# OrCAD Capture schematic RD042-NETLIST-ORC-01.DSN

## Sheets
1 3: size A3
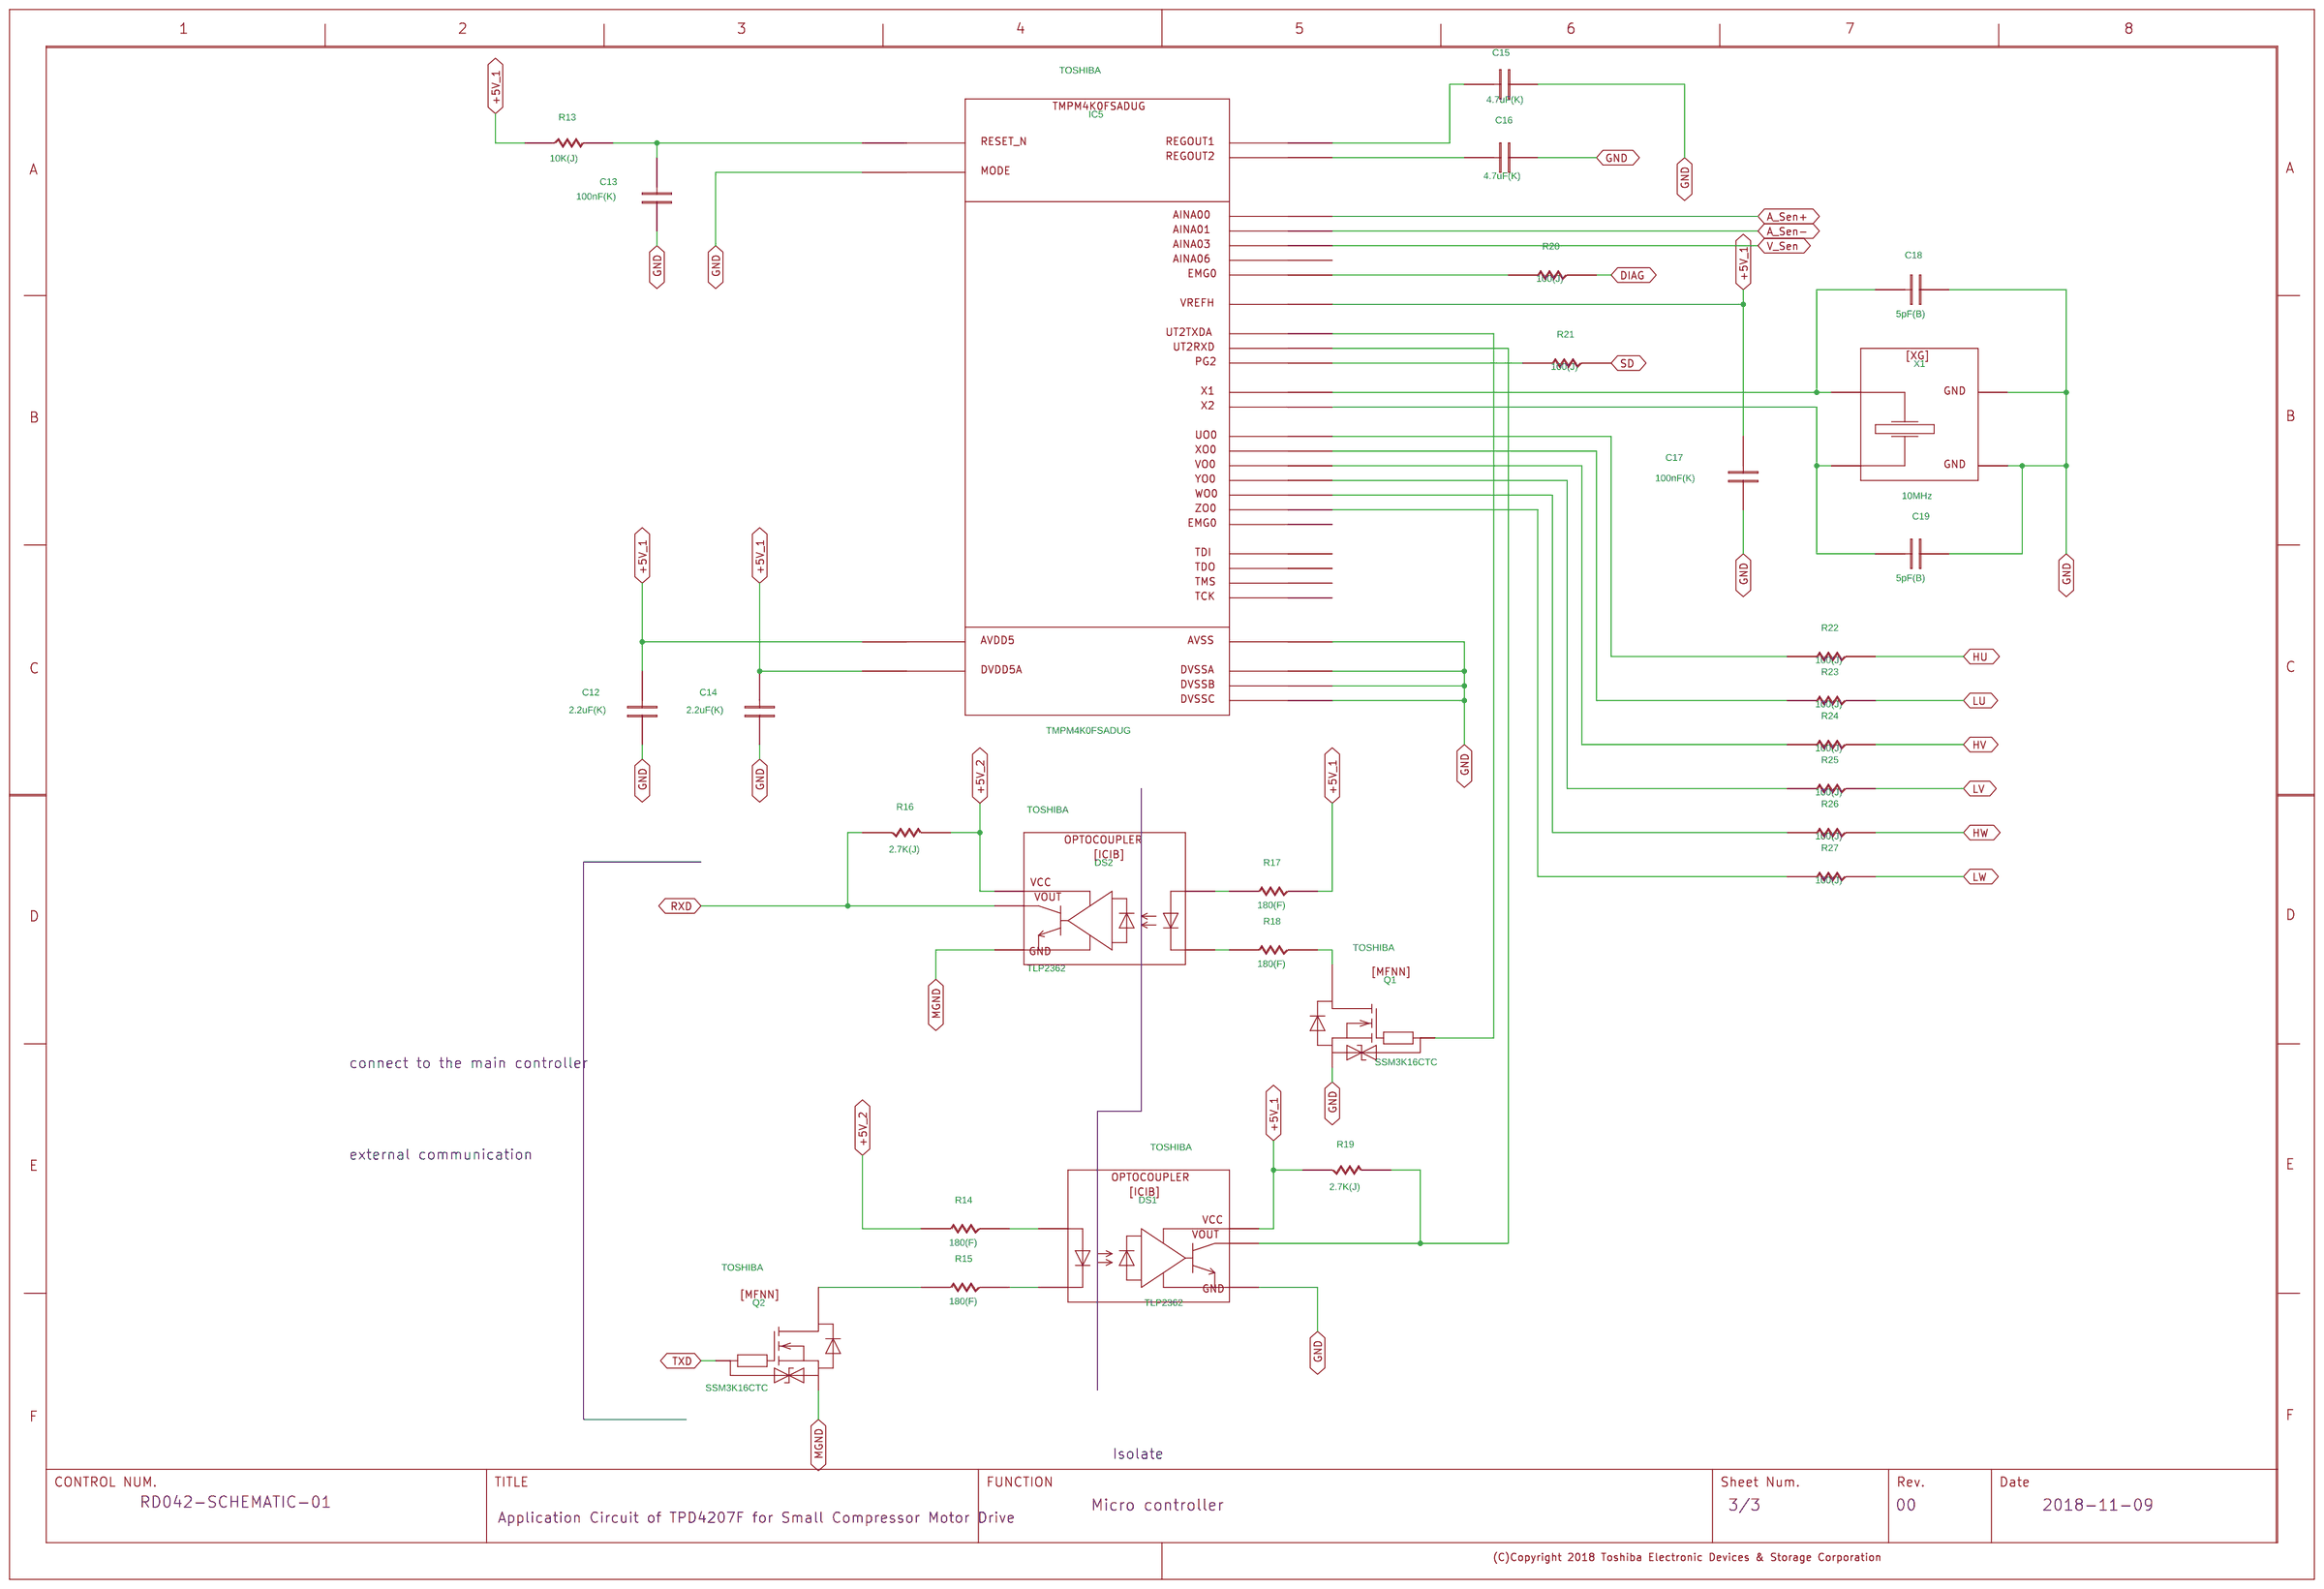
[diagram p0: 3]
2 2: size A3
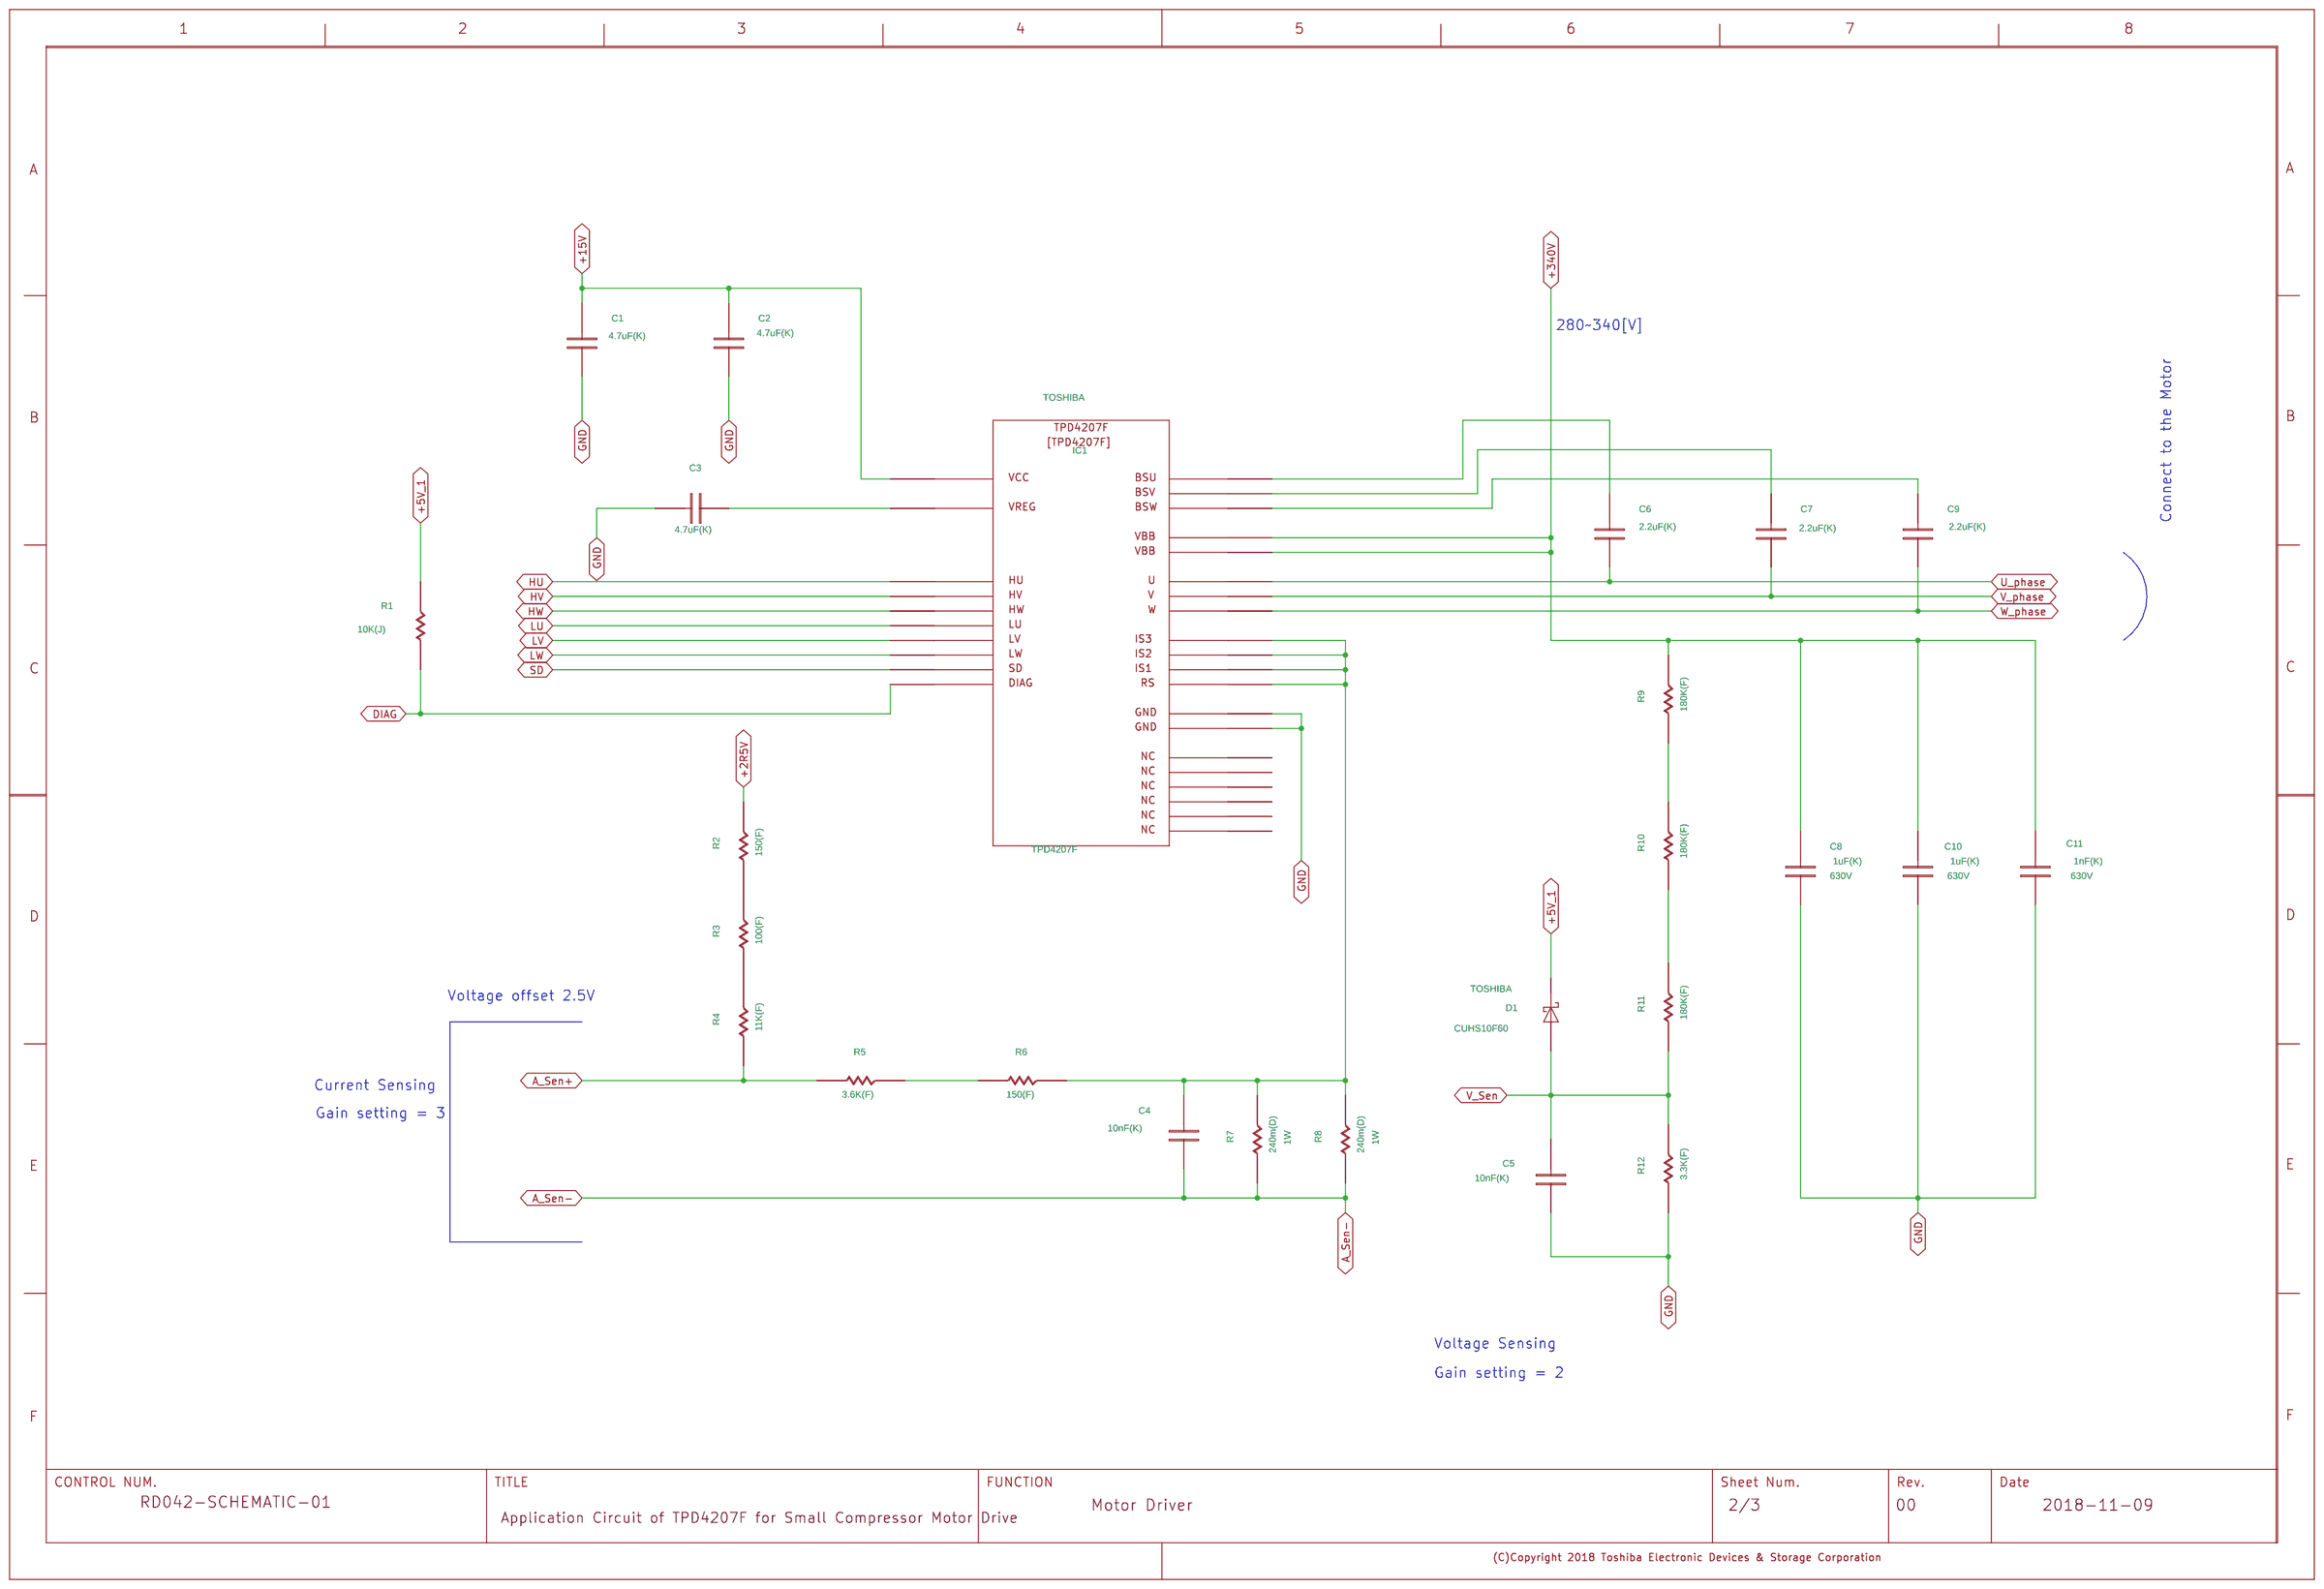
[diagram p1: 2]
3 1
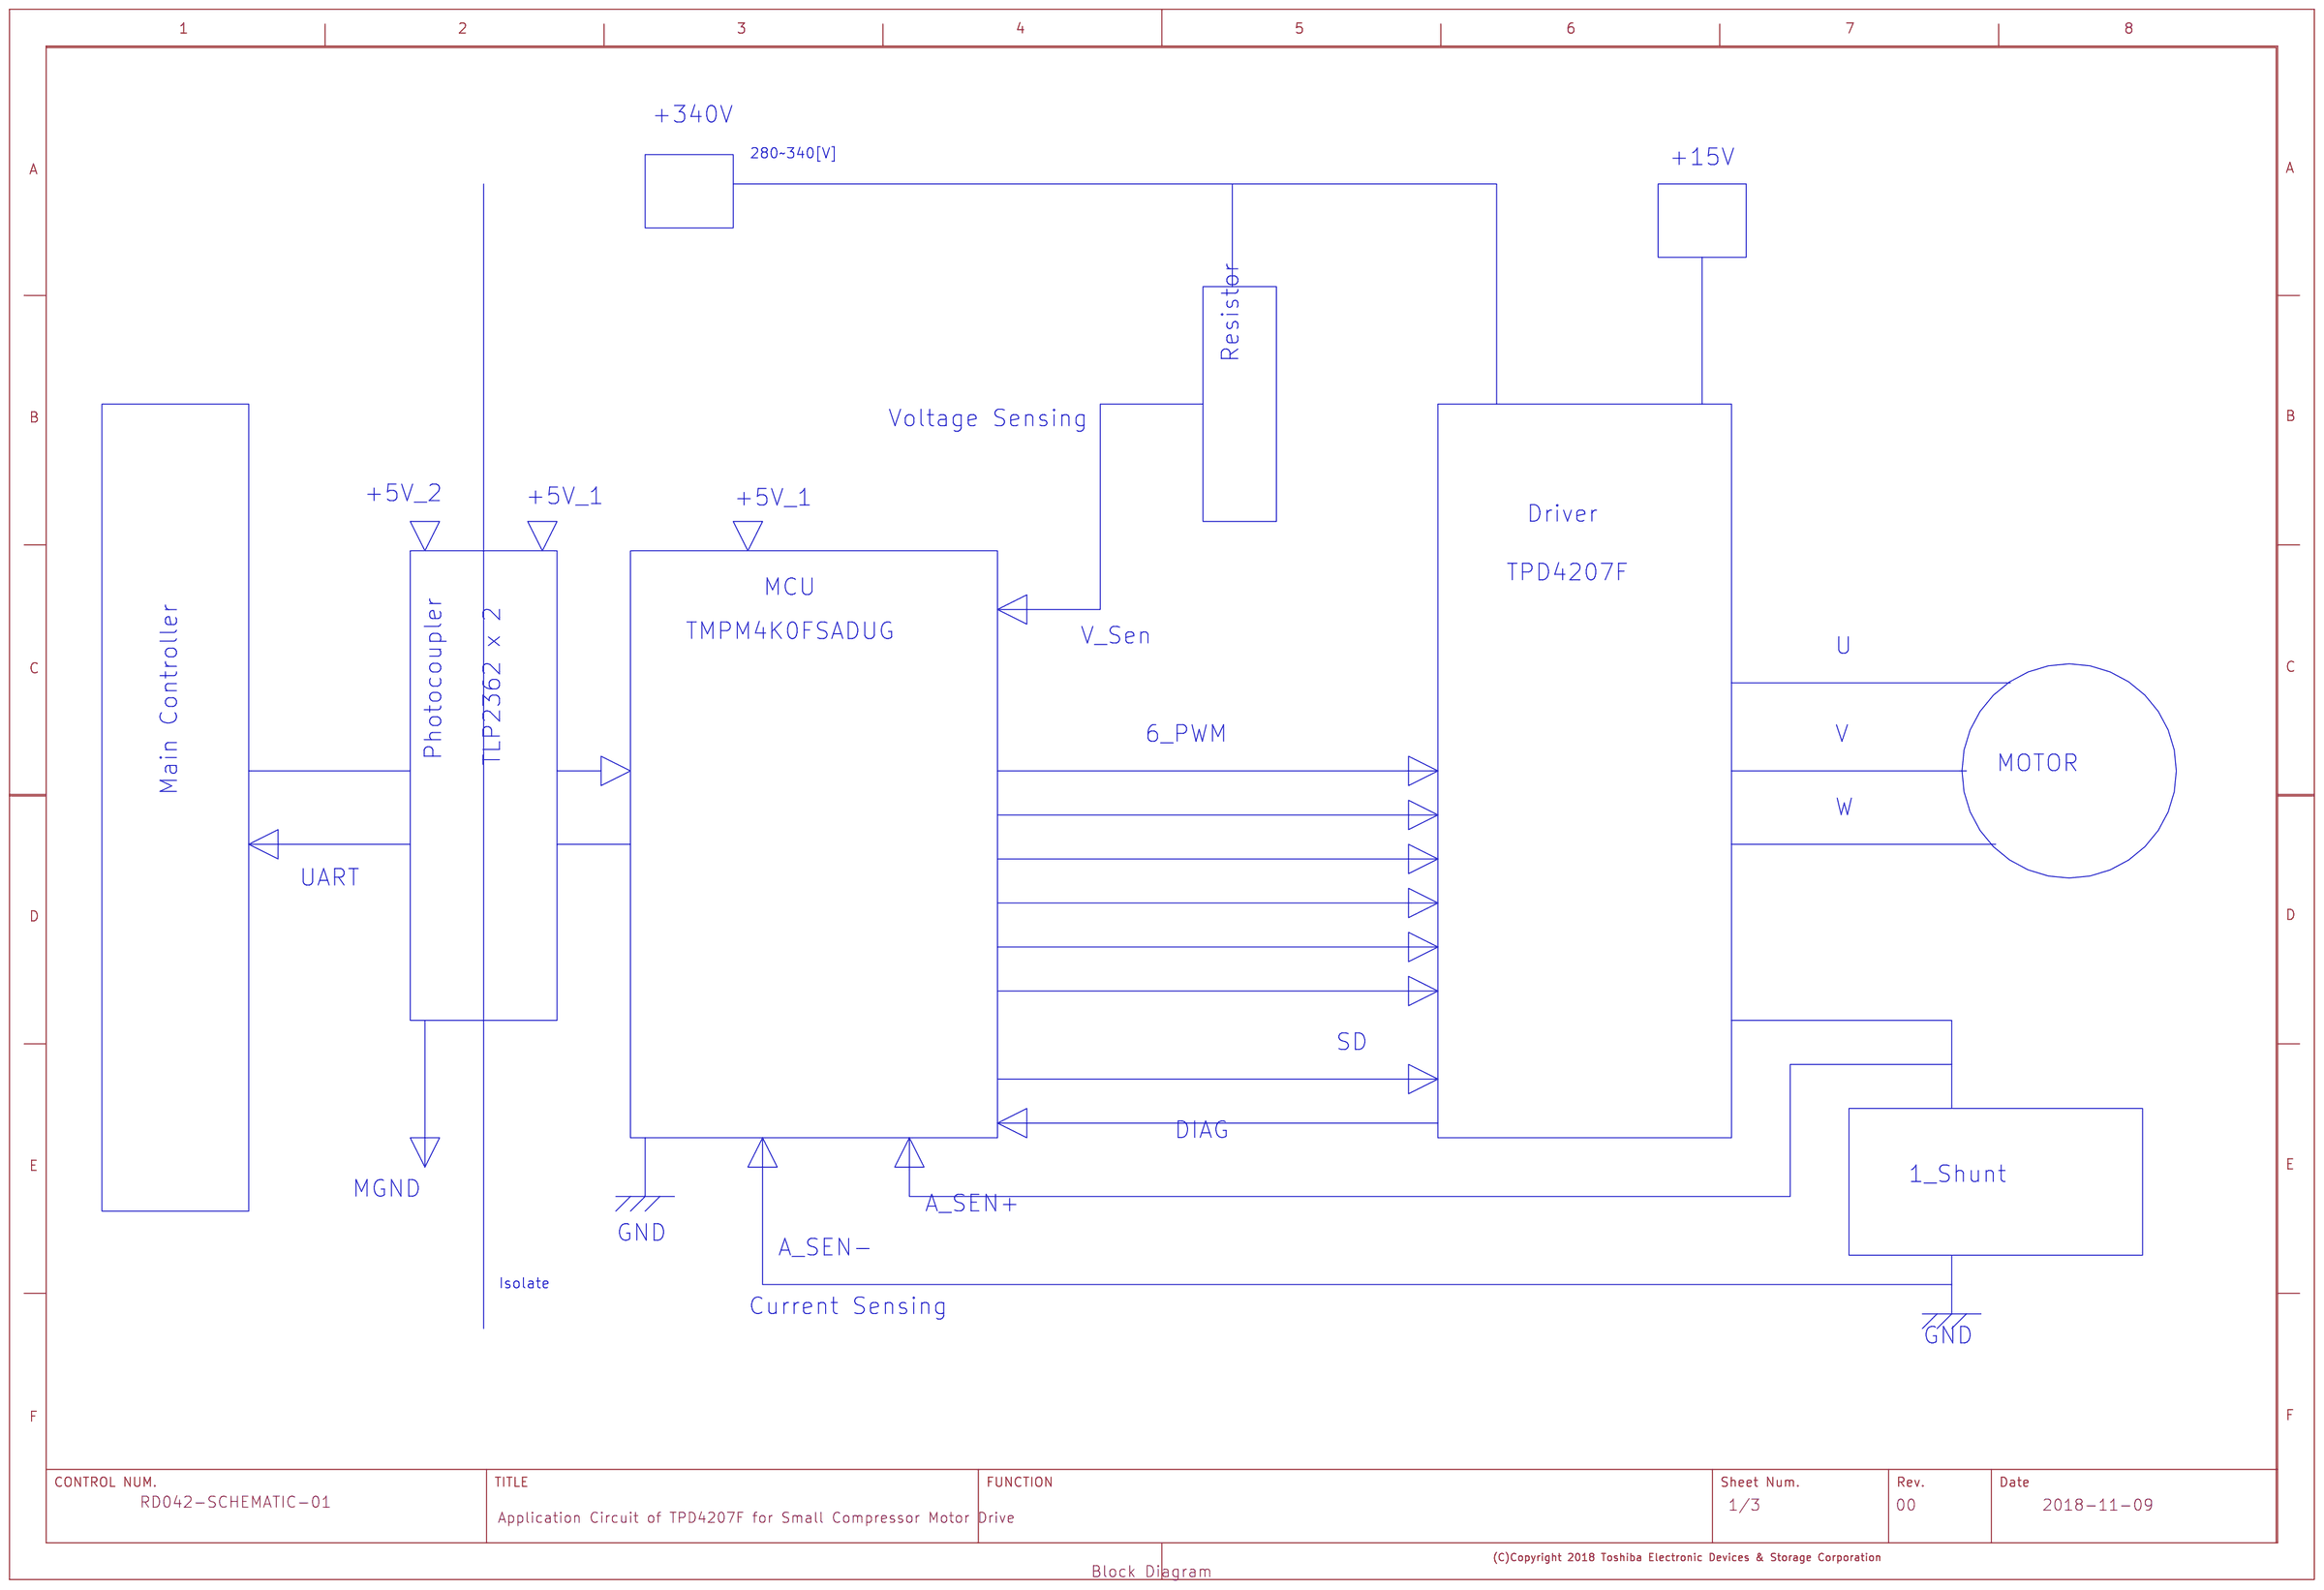
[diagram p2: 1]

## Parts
sheet 1
U?#2  WAKU_DEF100_2018
sheet 2
C1  C
C2  C
C3  C
C4  C
C5  C
C6  C
C7  C
C8  C
C9  C
C10  C
C11  C
D1  SBD
IC1  S-TPD4207F
R1  R
R2  R
R3  R
R4  R
R5  R
R6  R
R7  R
R8  R
R9  R
R10  R
R11  R
R12  R
U?#1  WAKU_DEF100_2018
sheet 3
C12  C
C13  C
C14  C
C15  C
C16  C
C17  C
C18  C
C19  C
DS1  ICIB
DS2  ICIB
IC5  TMPM4K0FSADUG-3
Q1  MFNN
Q2  MFNN
R13  R
R14  R
R15  R
R16  R
R17  R
R18  R
R19  R
R20  R
R21  R
R22  R
R23  R
R24  R
R25  R
R26  R
R27  R
U?#3  WAKU_DEF100_2018
X1  XG

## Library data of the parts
U?#2 = WAKU_DEF100_2018: AUTHOR: g4302510; COMPONENTTYPE: 2; DATE: 2018-11-09; DESIGNED: RD042-SCHEMATIC-01; DRAWINGNUMBER: RD042-SCHEMATIC-01; FUNCTION: Block Diagram; REVISION: 00; SAVEAREA0: -45080,-4508,463680,304612; SHEETNUMBER: 1/3; TIME: 10:32:20; TITLE: Application Circuit of TPD4207F for Small Compressor Motor Drive; UPDATEDATE: 2018/12/03; UPDATETIME: 17:07:27; UPDATEUSER: g4302510
C1-C3 = C: ADSCNVFLAG: ON; ADSCOMPONENTNAME: C_2012; ADSMODELNAME: s_GRM21BB31E475KA75L; ALLGREEN: 0:O[; CAPACITANCETOLE: K; CDBNAME: GDM030002448; CDMASTERCADCELG: KC0006; COMP: GDM030002448; COMPONENTNAME: GDM030002448_package; COMPONENTTYPE: 4; FNAPPROVALRESUG: B:i(GREEN); FNCANCELLATIONG: 0:Žg—p‰Â; FNENVIRONMANTRG: N:¢²¸; FNLEADFREETHET1GT2GMCTH1: 2_0_N; FUNCN: GDM030002448; GCOUNT: 1; ICX_PART_MODEL: CON_4.7U; MAXGCOUNT: 1; NOMINALCAPACITA: 4.7u; OUMECLASSIFICATION: ƒZƒ‰ƒ~ƒbƒNƒRƒ“ƒfƒ“ƒT; OUMEMAKER: MRT ºc»ì; OUMEMAKERKATAMEI: GRM21BB31E475KA75L; PMPRODUCTSTYPEG: HD1; QUADMODEL: CON_4.7U; RATEDVOLTAGE: 25; SIZECODESMD: 2012; SQ_PART_MODEL: CON_4.7U; TEMPCHARACTERI2: B; VAL1: 4.7uF(K); VAL2: 25V; VAL3: GRM21BB31E475KA75L
C4 C5 = C: ADSCNVFLAG: ON; ADSCOMPONENTNAME: C_3216; ADSMODELNAME: s_ECJ3FB2J103K; ALLGREEN: N:¢²¸; CAPACITANCETOLE: K; CDBNAME: K0301630; CDMASTERCADCELG: KC0014; COMP: K0301630; COMPONENTNAME: K0301630_package; COMPONENTTYPE: 4; FNAPPROVALRESUG: 5:bè(KR[h); FNCANCELLATIONG: 0:Žg—p‰Â; FNENVIRONMANTRG: N:¢²¸; FNLEADFREETHET1GT2GMCTH1: N_N_N; FUNCN: K0301630; GCOUNT: 1; ICX_PART_MODEL: CON_10N; MAXGCOUNT: 1; NOMINALCAPACITA: 10n; OUMECLASSIFICATION: ƒZƒ‰ƒ~ƒbƒNƒRƒ“ƒfƒ“ƒT; OUMEMAKER: NAE pi\jbNGNgjbNfoCX; OUMEMAKERKATAMEI: ECJ3FB2J103K; QUADMODEL: CON_10N; RATEDVOLTAGE: 630; SIZECODESMD: 3216; SQ_PART_MODEL: CON_10N; TEMPCHARACTERI2: B; VAL1: 10nF(K); VAL2: 630V; VAL3: ECJ3FB2J103K
C6 C7 C9 = C: ADSCNVFLAG: ON; ADSCOMPONENTNAME: C_2012; ADSMODELNAME: s_GRM219B31E225KA75D; ALLGREEN: 0:O[; CAPACITANCETOLE: K; CDBNAME: GDM030002425; CDMASTERCADCELG: KC0006; COMP: GDM030002425; COMPONENTNAME: GDM030002425_package; COMPONENTTYPE: 4; FNAPPROVALRESUG: B:i(GREEN); FNCANCELLATIONG: 0:Žg—p‰Â; FNENVIRONMANTRG: N:¢²¸; FNLEADFREETHET1GT2GMCTH1: 2_0_N; FUNCN: GDM030002425; GCOUNT: 1; ICX_PART_MODEL: CON_2.2U; MAXGCOUNT: 1; NOMINALCAPACITA: 2.2u; OUMECLASSIFICATION: ƒZƒ‰ƒ~ƒbƒNƒRƒ“ƒfƒ“ƒT; OUMEMAKER: MRT ºc»ì; OUMEMAKERKATAMEI: GRM219B31E225KA75D; PMPRODUCTSTYPEG: HD1; QUADMODEL: CON_2.2U; RATEDVOLTAGE: 25; SIZECODESMD: 2012; SQ_PART_MODEL: CON_2.2U; TEMPCHARACTERI2: B; VAL1: 2.2uF(K); VAL2: 25V; VAL3: GRM219B31E225KA75D
C8 C10 = C: ADSCNVFLAG: ON; ALLGREEN: 1:ñO[; CAPACITANCETOLE: K; CDBNAME: GDM030000013; CDMASTERCADCELG: RD0001; COMP: GDM030000013; COMPONENTNAME: GDM030000013_package; COMPONENTTYPE: 4; FNAPPROVALRESUG: 4:i; FNCANCELLATIONG: 0:Žg—p‰Â; FNENVIRONMANTRG: N:¢²¸; FNLEADFREETHET1GT2GMCTH1: 9_N_N; FUNCN: GDM030000013; GCOUNT: 1; ICX_PART_MODEL: CON_1U; MAXGCOUNT: 1; NOMINALCAPACITA: 1u; OUMECLASSIFICATION: ƒtƒBƒ‹ƒƒRƒ“ƒfƒ“ƒT; OUMEMAKER: NAE pi\jbNGNgjbNfoCX; OUMEMAKERKATAMEI: ECQE6105KF; QUADMODEL: CON_1U; RATEDVOLTAGE: 630; SIZECODESMD: DIP; SQ_PART_MODEL: CON_1U; VAL1: 1uF(K); VAL2: 630V; VAL3: ECQE6105KF
C11 = C: ADSCNVFLAG: ON; ALLGREEN: 1:ñO[; CAPACITANCETOLE: K; CDBNAME: GDM030000013; CDMASTERCADCELG: RD0001; COMP: GDM030000013; COMPONENTNAME: GDM030000013_package; COMPONENTTYPE: 4; FNAPPROVALRESUG: 4:i; FNCANCELLATIONG: 0:Žg—p‰Â; FNENVIRONMANTRG: N:¢²¸; FNLEADFREETHET1GT2GMCTH1: 9_N_N; FUNCN: GDM030000013; GCOUNT: 1; ICX_PART_MODEL: CON_1U; MAXGCOUNT: 1; NOMINALCAPACITA: 1u; OUMECLASSIFICATION: ƒtƒBƒ‹ƒƒRƒ“ƒfƒ“ƒT; OUMEMAKER: NAE pi\jbNGNgjbNfoCX; OUMEMAKERKATAMEI: ECQE6105KF; QUADMODEL: CON_1U; RATEDVOLTAGE: 630; SIZECODESMD: DIP; SQ_PART_MODEL: CON_1U; VAL1: 1nF(K); VAL2: 630V; VAL3: ECQE6105KF
D1 = SBD: ADSCNVFLAG: ON; ADSCOMPONENTNAME: D_SBD; ADSMODELNAME: s_CUS551V30; ALLGREEN: N:¢²¸; CDBNAME: K4200868; CDMASTERCADCELG: D81022; COMP: K4200868; COMPONENTNAME: K4200868_package; COMPONENTTYPE: 4; FNAPPROVALRESUG: 5:bè(KR[h); FNCANCELLATIONG: 0:Žg—p‰Â; FNENVIRONMANTRG: N:¢²¸; FNLEADFREETHET1GT2GMCTH1: N_N_N; FORWARDVOLTAGEM: 0; FUNCN: K4200868; GCOUNT: 1; MAXAVERAGEFORWA: 500m; MAXGCOUNT: 1; MAXREPETITIVEPE: 30; MAXREVERSEVOLTA: 0; MOUNTINGFORMSMD: SMD; OUMECLASSIFICATION: ¬p®¬fq/VbgLoA_CI[h; OUMEMAKER: TSB “ŒŽÅ; OUMEMAKERKATAMEI: CUS551V30; OUMEPARTTYPE: D; PEAKFORWARDVOLT: 380m; REVERSECURRENT: 100u; VAL1: CUHS10F60; VAL2: TOSHIBA; ZENERVOLTAGEMAX: 0; ZENERVOLTAGEMIN: 0
IC1 = S-TPD4207F: COMPONENTTYPE: 4; USERCOMPTEXT1: TPD4207F; USERCOMPTEXT3: TOSHIBA; VAL1: TPD4206F; VAL3: TPD4206F
R1 R13 = R: ADSCNVFLAG: ON; ADSCOMPONENTNAME: R_1005; ADSMODELNAME: s_CR10_103JV; ALLGREEN: N:¢²¸; CDBNAME: K0104074; CDMASTERCADCELG: KC0005; COMP: K0104074; COMPONENTNAME: K0104074_package; COMPONENTTYPE: 4; FNAPPROVALRESUG: 5:bè(KR[h); FNCANCELLATIONG: 0:Žg—p‰Â; FNENVIRONMANTRG: N:¢²¸; FNLEADFREETHET1GT2GMCTH1: N_N_N; FUNCN: K0104074; GCOUNT: 1; ICX_PART_MODEL: RES_10K; MAXGCOUNT: 1; MOUNTINGFORMSMD: SMD; NOMINALRESISTAN: 10K; OUMECLASSIFICATION: \ÊÀpÅèïRí; OUMEMAKER: HDK k¤dCHÆ; OUMEMAKERKATAMEI: CR10-103JV; POWERRATING: 63m; QUADMODEL: RES_10K; RESISTANCETOLER: J; SIZECODESMD: 1005; SQ_PART_MODEL: RES_10K; VAL1: 10K(J); VAL2: 63mW; VAL3: CR10-103JV
R2 R6 = R: ADSCNVFLAG: ON; ALLGREEN: N:¢²¸; CDBNAME: K0100279; CDMASTERCADCELG: DR824K; COMP: K0100279; COMPONENTNAME: K0100279_package; COMPONENTTYPE: 4; FNAPPROVALRESUG: 0:”­”Ô‚Ì‚Ý; FNCANCELLATIONG: 0:Žg—p‰Â; FNENVIRONMANTRG: 1:gpL(K§ÎÛO); FNLEADFREETHET1GT2GMCTH1: 3_1_2; FUNCN: K0100279; GCOUNT: 1; ICX_PART_MODEL: RES_150; MAXGCOUNT: 1; NOMINALRESISTAN: 150; OUMECLASSIFICATION: \ÊÀpÅèïRí; POWERRATING: 63m; QUADMODEL: RES_150; RESISTANCETOLER: F; SIZECODESMD: 1005; SQ_PART_MODEL: RES_150; VAL1: 150(F); VAL2: 63mW
R3 = R: ADSCNVFLAG: ON; ADSCOMPONENTNAME: R_0603; ADSMODELNAME: s_RC0201FR_07100RL; ALLGREEN: 0:O[; CDBNAME: GDM010004666; CDMASTERCADCELG: KC0054; COMP: GDM010004666; COMPONENTNAME: GDM010004666_package; COMPONENTTYPE: 4; FNAPPROVALRESUG: B:i(GREEN); FNCANCELLATIONG: 0:Žg—p‰Â; FNENVIRONMANTRG: 1:gpL(K§ÎÛO); FNLEADFREETHET1GT2GMCTH1: 3_0_N; FUNCN: GDM010004666; GANSWERREV: 9; GCOUNT: 1; ICX_PART_MODEL: RES_100; MAXGCOUNT: 1; MOUNTINGFORMSMD: SMD; NOMINALRESISTAN: 100; OUMECLASSIFICATION: \ÊÀpÅèïRí; OUMEMAKER: YGO ƒ„ƒQƒI; OUMEMAKERKATAMEI: RC0201FR-07100RL; PMPRODUCTSTYPEG: HD1; POWERRATING: 50m; QUADMODEL: RES_100; RESISTANCETOLER: F; SIZECODESMD: 0603; SQ_PART_MODEL: RES_100; VAL1: 100(F); VAL2: 50mW; VAL3: RC0201FR-07100RL
R4 = R: ADSCNVFLAG: ON; ADSCOMPONENTNAME: R_0603; ADSMODELNAME: s_CR1_20_113DV_HSF; ALLGREEN: 0:O[; CDBNAME: GDM010004057; CDMASTERCADCELG: KC0054; COMP: GDM010004057; COMPONENTNAME: GDM010004057_package; COMPONENTTYPE: 4; FNAPPROVALRESUG: B:i(GREEN); FNCANCELLATIONG: 0:Žg—p‰Â; FNENVIRONMANTRG: 1:gpL(K§ÎÛO); FNLEADFREETHET1GT2GMCTH1: 3_2_N; FUNCN: GDM010004057; GANSWERREV: 8; GCOUNT: 1; ICX_PART_MODEL: RES_11K; MAXGCOUNT: 1; MOUNTINGFORMSMD: SMD; NOMINALRESISTAN: 11K; OUMECLASSIFICATION: \ÊÀpÅèïRí; OUMEMAKER: HDK k¤dCHÆ; OUMEMAKERKATAMEI: CR1/20 113DV HSF; PMPRODUCTSTYPEG: HD1; POWERRATING: 50m; QUADMODEL: RES_11K; RESISTANCETOLER: D; SIZECODESMD: 0603; SQ_PART_MODEL: RES_11K; VAL1: 11K(F); VAL2: 50mW; VAL3: CR1/20 113DV HSF
R5 = R: ADSCNVFLAG: ON; ADSCOMPONENTNAME: R_1005; ADSMODELNAME: s_CR10_362JV; ALLGREEN: N:¢²¸; CDBNAME: K0104081; CDMASTERCADCELG: KC0005; COMP: K0104081; COMPONENTNAME: K0104081_package; COMPONENTTYPE: 4; FNAPPROVALRESUG: 5:bè(KR[h); FNCANCELLATIONG: 0:Žg—p‰Â; FNENVIRONMANTRG: N:¢²¸; FNLEADFREETHET1GT2GMCTH1: N_N_N; FUNCN: K0104081; GCOUNT: 1; ICX_PART_MODEL: RES_3.6K; MAXGCOUNT: 1; MOUNTINGFORMSMD: SMD; NOMINALRESISTAN: 3.6K; OUMECLASSIFICATION: \ÊÀpÅèïRí; OUMEMAKER: HDK k¤dCHÆ; OUMEMAKERKATAMEI: CR10-362JV; POWERRATING: 63m; QUADMODEL: RES_3.6K; RESISTANCETOLER: J; SIZECODESMD: 1005; SQ_PART_MODEL: RES_3.6K; VAL1: 3.6K(F); VAL2: 63mW; VAL3: CR10-362JV
R7 R8 = R: ADSCNVFLAG: ON; ADSCOMPONENTNAME: R_6332; ADSMODELNAME: s_SL1TTER240D; ALLGREEN: 0:O[; CDBNAME: GDM010002924; CDMASTERCADCELG: DR822R; COMP: GDM010002924; COMPONENTNAME: GDM010002924_package; COMPONENTTYPE: 4; FNAPPROVALRESUG: B:i(GREEN); FNCANCELLATIONG: 0:Žg—p‰Â; FNENVIRONMANTRG: 1:gpL(K§ÎÛO); FNLEADFREETHET1GT2GMCTH1: 3_2_N; FUNCN: GDM010002924; GANSWERREV: 8; GCOUNT: 1; ICX_PART_MODEL: RES_240M; MAXGCOUNT: 1; MOUNTINGFORMSMD: SMD; NOMINALRESISTAN: 240m; OUMECLASSIFICATION: \ÊÀpÅèïRí; OUMEMAKER: KOA R[A; OUMEMAKERKATAMEI: SL1TTER240D; PMPRODUCTSTYPEG: SV1; POWERRATING: 1; QUADMODEL: RES_240M; RESISTANCETOLER: D; SIZECODESMD: 6332; SQ_PART_MODEL: RES_240M; VAL1: 240m(D); VAL2: 1W; VAL3: SL1TTER240D
R9-R11 = R: ADSCNVFLAG: ON; ADSCOMPONENTNAME: R_1608; ADSMODELNAME: s_RPC05T184F; ALLGREEN: N:¢²¸; CDBNAME: K0101881; CDMASTERCADCELG: KC0008; COMP: K0101881; COMPONENTNAME: K0101881_package; COMPONENTTYPE: 4; FNAPPROVALRESUG: 5:bè(KR[h); FNCANCELLATIONG: 0:Žg—p‰Â; FNENVIRONMANTRG: N:¢²¸; FNLEADFREETHET1GT2GMCTH1: N_N_N; FUNCN: K0101881; GCOUNT: 1; ICX_PART_MODEL: RES_180K; MAXGCOUNT: 1; MOUNTINGFORMSMD: SMD; NOMINALRESISTAN: 180K; OUMECLASSIFICATION: \ÊÀpÅèïRí; OUMEMAKER: TID ‘¾—zŽÐ“d‹C; OUMEMAKERKATAMEI: RPC05T184F; POWERRATING: 100m; QUADMODEL: RES_180K; RESISTANCETOLER: F; SIZECODESMD: 1608; SQ_PART_MODEL: RES_180K; VAL1: 180K(F); VAL2: 100mW; VAL3: RPC05T184F
R12 = R: ADSCNVFLAG: ON; ADSCOMPONENTNAME: R_1608; ADSMODELNAME: s_ERJ3GEYF332V; ALLGREEN: 0:O[; CDBNAME: GDM010001005; CDMASTERCADCELG: DR802R; COMP: GDM010001005; COMPONENTNAME: GDM010001005_package; COMPONENTTYPE: 4; FNAPPROVALRESUG: B:i(GREEN); FNCANCELLATIONG: 0:Žg—p‰Â; FNENVIRONMANTRG: 1:gpL(K§ÎÛO); FNLEADFREETHET1GT2GMCTH1: 3_1_N; FUNCN: GDM010001005; GANSWERREV: 6; GCOUNT: 1; ICX_PART_MODEL: RES_3.3K; MAXGCOUNT: 1; MOUNTINGFORMSMD: SMD; NOMINALRESISTAN: 3.3K; OUMECLASSIFICATION: \ÊÀpÅèïRí; OUMEMAKER: NAE pi\jbNGNgjbNfoCX; OUMEMAKERKATAMEI: ERJ3GEYF332V; POWERRATING: 63m; QUADMODEL: RES_3.3K; RESISTANCETOLER: F; SIZECODESMD: 1608; SQ_PART_MODEL: RES_3.3K; VAL1: 3.3K(F); VAL2: 63mW; VAL3: ERJ3GEYF332V
U?#1 = WAKU_DEF100_2018: AUTHOR: g4302510; COMPONENTTYPE: 2; DATE: 2018-11-09; DRAWINGNUMBER: RD042-SCHEMATIC-01; FUNCTION: Motor Driver; REVISION: 00; SAVEAREA0: -45080,-4508,463680,304612; SHEETNUMBER: 2/3; TIME: 15:28:53; TITLE: Application Circuit of TPD4207F for Small Compressor Motor Drive; UPDATEDATE: 2018/12/03; UPDATETIME: 17:17:17; UPDATEUSER: g4302510
C12 C14 = C: ADSCNVFLAG: ON; ADSCOMPONENTNAME: C_1005; ADSMODELNAME: s_C1005X5R1H102K050BA; ALLGREEN: N:¢²¸; CAPACITANCETOLE: K; CDBNAME: K0303063; CDMASTERCADCELG: KC0005; COMP: K0303063; COMPONENTNAME: K0303063_package; COMPONENTTYPE: 4; FNAPPROVALRESUG: 5:bè(KR[h); FNCANCELLATIONG: 0:Žg—p‰Â; FNENVIRONMANTRG: N:¢²¸; FNLEADFREETHET1GT2GMCTH1: N_N_N; FUNCN: K0303063; GCOUNT: 1; ICX_PART_MODEL: CON_1N; MAXGCOUNT: 1; NOMINALCAPACITA: 1n; OUMECLASSIFICATION: ƒZƒ‰ƒ~ƒbƒNƒRƒ“ƒfƒ“ƒT; OUMEMAKER: TDK ‚s‚c‚j; OUMEMAKERKATAMEI: C1005X5R1H102K050BA; QUADMODEL: CON_1N; RATEDVOLTAGE: 50; SIZECODESMD: 1005; SQ_PART_MODEL: CON_1N; VAL1: 2.2uF(K); VAL2: 50V; VAL3: C1005X5R1H102K050BA
C13 C17 = C: ADSCNVFLAG: ON; ADSCOMPONENTNAME: C_1005; ADSMODELNAME: s_GRM155R71E104KE14D; ALLGREEN: N:¢²¸; CAPACITANCETOLE: K; CDBNAME: K0302640; CDMASTERCADCELG: KC0005; COMP: K0302640; COMPONENTNAME: K0302640_package; COMPONENTTYPE: 4; FNAPPROVALRESUG: 5:bè(KR[h); FNCANCELLATIONG: 0:Žg—p‰Â; FNENVIRONMANTRG: N:¢²¸; FNLEADFREETHET1GT2GMCTH1: N_N_N; FUNCN: K0302640; GCOUNT: 1; ICX_PART_MODEL: CON_100N; MAXGCOUNT: 1; NOMINALCAPACITA: 100n; OUMECLASSIFICATION: ƒZƒ‰ƒ~ƒbƒNƒRƒ“ƒfƒ“ƒT; OUMEMAKER: MRT ºc»ì; OUMEMAKERKATAMEI: GRM155R71E104KE14D; QUADMODEL: CON_100N; RATEDVOLTAGE: 25; SIZECODESMD: 1005; SQ_PART_MODEL: CON_100N; VAL1: 100nF(K); VAL2: 25V; VAL3: GRM155R71E104KE14D
C15 C16 = C: ADSCNVFLAG: ON; ADSCOMPONENTNAME: C_1005; ADSMODELNAME: s_C1005X5R1A475K; ALLGREEN: N:¢²¸; CAPACITANCETOLE: K; CDBNAME: K0302862; CDMASTERCADCELG: KC0005; COMP: K0302862; COMPONENTNAME: K0302862_package; COMPONENTTYPE: 4; FNAPPROVALRESUG: 5:bè(KR[h); FNCANCELLATIONG: 0:Žg—p‰Â; FNENVIRONMANTRG: N:¢²¸; FNLEADFREETHET1GT2GMCTH1: N_N_N; FUNCN: K0302862; GCOUNT: 1; ICX_PART_MODEL: CON_4.7U; MAXGCOUNT: 1; NOMINALCAPACITA: 4.7u; OUMECLASSIFICATION: ƒZƒ‰ƒ~ƒbƒNƒRƒ“ƒfƒ“ƒT; OUMEMAKER: TDK ‚s‚c‚j; OUMEMAKERKATAMEI: C1005X5R1A475K; QUADMODEL: CON_4.7U; RATEDVOLTAGE: 10; SIZECODESMD: 1005; SQ_PART_MODEL: CON_4.7U; VAL1: 4.7uF(K); VAL2: 10V; VAL3: C1005X5R1A475K
C18 C19 = C: ADSCNVFLAG: ON; ADSCOMPONENTNAME: C_1005; ADSMODELNAME: s_CL05C050BB5NNPC; ALLGREEN: 0:O[; CAPACITANCETOLE: B; CDBNAME: GDM030002325; CDMASTERCADCELG: KC0005; COMP: GDM030002325; COMPONENTNAME: GDM030002325_package; COMPONENTTYPE: 4; FNAPPROVALRESUG: B:i(GREEN); FNCANCELLATIONG: 0:Žg—p‰Â; FNENVIRONMANTRG: 0:Žg—p–³; FNLEADFREETHET1GT2GMCTH1: 3_2_N; FUNCN: GDM030002325; GANSWERREV: 11; GCOUNT: 1; ICX_PART_MODEL: CON_5P; MAXGCOUNT: 1; NOMINALCAPACITA: 5p; OUMECLASSIFICATION: ƒZƒ‰ƒ~ƒbƒNƒRƒ“ƒfƒ“ƒT; OUMEMAKER: SAM O¯d@; OUMEMAKERKATAMEI: CL05C050BB5NNPC; PMPRODUCTSTYPEG: DME; QUADMODEL: CON_5P; RATEDVOLTAGE: 50; SIZECODESMD: 1005; SQ_PART_MODEL: CON_5P; VAL1: 5pF(B); VAL2: 50V; VAL3: CL05C050BB5NNPC
DS1 DS2 = ICIB: ADSCNVFLAG: ON; ALLGREEN: 0:O[; CDBNAME: GAS440000002; CDMASTERCADCELG: MM0171; COMP: GAS440000002; COMPONENTNAME: GAS440000002_package; COMPONENTTYPE: 4; FNAPPROVALRESUG: H:i[AS]; FNCANCELLATIONG: 0:Žg—p‰Â; FNENVIRONMANTRG: 0:Žg—p–³; FNLEADFREETHET1GT2GMCTH1: 2_0_N; FUNCN: GAS440000002; GANSWERREV: 1; GCOUNT: 1; MAXDCFORWARDCUR: 25m; MAXDCREVERSEVOL: 0; MAXGCOUNT: 1; MOUNTINGFORMSMD: SMD; OUMECLASSIFICATION: ICƒJƒvƒ‰; OUMEMAKER: TSB “ŒŽÅ; OUMEMAKERKATAMEI: TLP9104A(AST-TL,F)@@; OUMEPARTTYPE: DS; PMPRODUCTSTYPEG: HEV; VAL2: TOSHIBA; VAL3: TLP2362
IC5 = TMPM4K0FSADUG-3: COMPONENTTYPE: 4; USERCOMPTEXT1: TOSHIBA; VAL1: TMPM4K0FSADUG
Q1 Q2 = MFNN: ADSCNVFLAG: ON; ADSCOMPONENTNAME: Q_MFNN; ADSMODELNAME: s_SSM3K35CT; ALLGREEN: N:¢²¸; CDBNAME: K4101031; CDMASTERCADCELG: LA0079; COMP: K4101031; COMPONENTNAME: K4101031_package; COMPONENTTYPE: 4; FNAPPROVALRESUG: 5:bè(KR[h); FNCANCELLATIONG: 0:Žg—p‰Â; FNENVIRONMANTRG: N:¢²¸; FNLEADFREETHET1GT2GMCTH1: N_N_N; FUNCN: K4101031; GCOUNT: 1; MAXCBVOLTAGE: 0; MAXCEVOLTAGE: 0; MAXCOLLECTORCUR: 0; MAXDRAINCURRENT: 180m; MAXDSVOLTAGE: 20; MAXEBVOLTAGE: 0; MAXGATECURRENT: 0; MAXGCOUNT: 1; MAXGDVOLTAGE: 0; MAXGSVOLTAGE: 10; MOUNTINGFORMSMD: SMD; OUMECLASSIFICATION: Nƒ`ƒƒƒ“ƒlƒ‹MOS-FET; OUMEMAKER: TSB “ŒŽÅ; OUMEMAKERKATAMEI: SSM3K35CT; OUMEPARTTYPE: Q; VAL1: SSM3K16CTC; VAL2: TOSHIBA; VAL3: SSM3K16CTC
R14 R15 R17 R18 = R: ADSCNVFLAG: ON; ADSCOMPONENTNAME: R_1005; ADSMODELNAME: s_TSR16GF181V; ALLGREEN: 1:ñO[; CDBNAME: GDM010000348; CDMASTERCADCELG: KC0005; COMP: GDM010000348; COMPONENTNAME: GDM010000348_package; COMPONENTTYPE: 4; FNAPPROVALRESUG: 7:i(MCÐÌÝ); FNCANCELLATIONG: 0:Žg—p‰Â; FNENVIRONMANTRG: 1:gpL(K§ÎÛO); FNLEADFREETHET1GT2GMCTH1: N_N_N; FUNCN: GDM010000348; GCOUNT: 1; ICX_PART_MODEL: RES_180; MAXGCOUNT: 1; MOUNTINGFORMSMD: SMD; NOMINALRESISTAN: 180; OUMECLASSIFICATION: \ÊÀpÅèïRí; OUMEMAKER: TAT §RÈwHÆ; OUMEMAKERKATAMEI: TSR16GF181V; PMPRODUCTSTYPEG: MP1; POWERRATING: 63m; QUADMODEL: RES_180; RESISTANCETOLER: F; SIZECODESMD: 1005; SQ_PART_MODEL: RES_180; VAL1: 180(F); VAL2: 63mW; VAL3: TSR16GF181V
R16 R19 = R: ADSCNVFLAG: ON; ADSCOMPONENTNAME: R_1005; ADSMODELNAME: s_RK73B1ETTP272J@@; ALLGREEN: N:¢²¸; CDBNAME: K0104156; CDMASTERCADCELG: KC0131; COMP: K0104156; COMPONENTNAME: K0104156_package; COMPONENTTYPE: 4; FNAPPROVALRESUG: 5:bè(KR[h); FNCANCELLATIONG: 0:Žg—p‰Â; FNENVIRONMANTRG: N:¢²¸; FNLEADFREETHET1GT2GMCTH1: N_N_N; FUNCN: K0104156; GCOUNT: 1; ICX_PART_MODEL: RES_2.7K; MAXGCOUNT: 1; MOUNTINGFORMSMD: SMD; NOMINALRESISTAN: 2.7K; OUMECLASSIFICATION: \ÊÀpÅèïRí; OUMEMAKER: KOA R[A; OUMEMAKERKATAMEI: RK73B1ETTP272J@@; POWERRATING: 63m; QUADMODEL: RES_2.7K; RESISTANCETOLER: J; SIZECODESMD: 1005; SQ_PART_MODEL: RES_2.7K; VAL1: 2.7K(J); VAL2: 63mW; VAL3: RK73B1ETTP272J@@
R20-R27 = R: ADSCNVFLAG: ON; ADSCOMPONENTNAME: R_1005; ADSMODELNAME: s_CR10_101JV; ALLGREEN: N:¢²¸; CDBNAME: K0104072; CDMASTERCADCELG: KC0005; COMP: K0104072; COMPONENTNAME: K0104072_package; COMPONENTTYPE: 4; FNAPPROVALRESUG: 5:bè(KR[h); FNCANCELLATIONG: 0:Žg—p‰Â; FNENVIRONMANTRG: N:¢²¸; FNLEADFREETHET1GT2GMCTH1: N_N_N; FUNCN: K0104072; GCOUNT: 1; ICX_PART_MODEL: RES_100; MAXGCOUNT: 1; MOUNTINGFORMSMD: SMD; NOMINALRESISTAN: 100; OUMECLASSIFICATION: \ÊÀpÅèïRí; OUMEMAKER: HDK k¤dCHÆ; OUMEMAKERKATAMEI: CR10-101JV; POWERRATING: 63m; QUADMODEL: RES_100; RESISTANCETOLER: J; SIZECODESMD: 1005; SQ_PART_MODEL: RES_100; VAL1: 100(J); VAL2: 63mW; VAL3: CR10-101JV
U?#3 = WAKU_DEF100_2018: AUTHOR: g4302510; COMPONENTTYPE: 2; DATE: 2018-11-09; DRAWINGNUMBER: RD042-SCHEMATIC-01; FUNCTION: Micro controller; PAGENUMBER: 2/2; REVISION: 00; SAVEAREA0: -45080,-4508,463680,304612; SHEETNUMBER: 3/3; TIME: 18:40:31; TITLE: Application Circuit of TPD4207F for Small Compressor Motor Drive; UPDATEDATE: 2018/12/03; UPDATETIME: 17:07:27; UPDATEUSER: g4302510
X1 = XG: ADSCNVFLAG: ON; ALLGREEN: N:¢²¸; CDBNAME: K1000665; CDMASTERCADCELG: KC0077; COMP: K1000665; COMPONENTNAME: K1000665_package; COMPONENTTYPE: 4; FNAPPROVALRESUG: 5:bè(KR[h); FNCANCELLATIONG: 0:Žg—p‰Â; FNENVIRONMANTRG: N:¢²¸; FNLEADFREETHET1GT2GMCTH1: N_N_N; FREQTEMPCHARAC1: 0; FREQTEMPCHARAC2: 0; FREQUENCYDEVIA1: 0; FREQUENCYDEVIA2: 7; FUNCN: K1000665; GCOUNT: 1; MAXGCOUNT: 1; MOUNTINGFORMSMD: SMD; NOMINALFREQ: 10M; OUMECLASSIFICATION: »U®q; OUMEMAKER: FSG o[GebN; OUMEMAKERKATAMEI: FCX-04C-10.000MHZ; OUMEPARTTYPE: X; VAL1: 10MHz; VAL2: 7ppm; VAL3: FCX-04C-10.000MHZ

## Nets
+5V_1: C12.2 C14.2 C17.2 D1.C DS1.6 IC5.3 IC5.24 IC5.25 R1.2 R13.2 R17.2 R19.2
+5V_2: DS2.6 R14.1 R16.1
+15V: C1.2 C2.2 IC1.5
+340V: C8.2 C10.2 C11.2 IC1.23 IC1.24 R9.2
GND: C1.1 C2.1 C3.2 C5.1 C8.1 C10.1 C11.1 C12.1 C13.1 C14.1 C15.1 C16.1 C17.1 C18.1 C19.1 DS1.4 IC1.8 IC1.16 IC5.6 IC5.17 IC5.18 IC5.26 IC5.30 Q1.S R12.1 X1.2 X1.4
+2R5V: R2.2
A_Sen+: IC5.19 R4.1 R5.1
A_Sen-: C4.1 IC5.20 R7.1 R8.1
DIAG: IC1.4 R1.1 R20.2
HU: IC1.15 R22.2
HV: IC1.14 R24.2
HW: IC1.13 R26.2
LU: IC1.12 R23.2
LV: IC1.11 R25.2
LW: IC1.10 R27.2
MGND: DS2.4 Q2.S
RXD: DS2.5 R16.2
SD: IC1.7 R21.2
TXD: Q2.G
U_phase: C6.1 IC1.30
V_phase: C7.1 IC1.26
V_Sen: C5.2 D1.A IC5.21 R11.1 R12.2
W_phase: C9.1 IC1.21
N00701: C6.2 IC1.29
N00711: C7.2 IC1.25
N00721: C9.2 IC1.22
N00779: R10.1 R11.2
N00783: R9.1 R10.2
N00801: C3.1 IC1.6
N00853: C4.2 IC1.9 IC1.20 IC1.27 IC1.28 R6.2 R7.2 R8.2
N00911: R5.2 R6.1
N01106: R2.1 R3.2
N01107: R3.1 R4.2
N01735: IC5.16 R22.1
N01743: IC5.14 R24.1
N01751: IC5.15 R23.1
N01759: IC5.13 R25.1
N01767: IC5.12 R26.1
N01775: IC5.11 R27.1
N01825: C16.2 IC5.4
N01829: C18.2 IC5.7 X1.1
N01839: C19.2 IC5.8 X1.3
N01887: DS2.3 R18.1
N01891: DS1.1 R14.2
N01895: DS2.1 R17.1
N01919: C15.2 IC5.5
N01927: DS1.3 R15.2
N01955: Q2.D R15.1
N01965: Q1.D R18.2
N01975: C13.2 IC5.9 R13.1
N02015: IC5.23 R20.1
N02019: IC5.29 R21.1
N02023: DS1.5 IC5.28 R19.1
N02037: IC5.27 Q1.G

Not connected (* = marked no-connect by the designer): IC1 1 2 3 17 18 19; IC5 1 2 10 22 31 32

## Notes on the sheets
sheet 1
- connect to the main controller
- external communication
- Isolate
sheet 2
- 280~340[V]
- Connect to the Motor
- Voltage offset 2.5V
- Current Sensing
- Gain setting = 3
- Voltage Sensing
- Gain setting = 2
sheet 3
- +340V
- 280~340[V]
- +15V
- Resistor
- Voltage Sensing
- +5V_2
- +5V_1
- +5V_1
- Driver
- TPD4207F
- MCU
- TMPM4K0FSADUG
- V_Sen
- U
- 6_PWM
- V
- MOTOR
- Photocoupler
- TLP2362 x 2
- Main Controller
- W
- UART
- SD
- DIAG
- 1_Shunt
- MGND
- A_SEN+
- GND
- A_SEN-
- Isolate
- Current Sensing
- GND
